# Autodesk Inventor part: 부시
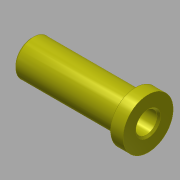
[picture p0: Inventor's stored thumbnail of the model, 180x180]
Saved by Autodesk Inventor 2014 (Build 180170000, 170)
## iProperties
Created: 2016-11
Part Number: 부시
Material: 강철, 연강
Document SubType Name: Modeling
Designer: mduedu
Density: 1 g/cm^3
Appearance: Yellow
Author: mduedu
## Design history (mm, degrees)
sketch "스케치1"
  geometry: L1 (0, 0)-(65, 0); L2 (65, 0)-(65, 14); L3 (65, 14)-(58, 14); L4 (58, 14)-(58, 10); L5 (58, 10)-(0, 10); L6 (0, 10)-(0, 0)
  constraints: 12 end point, 3 parallel, 2 perpendicular, 1 horizontal
  dimensions: "d0" = 65 distance of L1.start L1.end; "d1" = 7 distance of L2.end L3.end; "d2" = 28 diameter of L3 L1; "d3" = 20 diameter of L5 L1
revolve "회전1" sketch "스케치1" stored, may be unused: angle "d4" = 90 deg
hole "구멍1" diameter "d7" = 12; stored, may be unused: countersink angle "d11" = 90 deg, drill point angle "d13" = 118 deg; dims "d5" = 10, "d6" = 10, "d8" = 6, "d9" = 4, "d10" = 2, "d12" = 8
chamfer "모따기1" distance "d14" = 1; stored, may be unused: second distance "d15" = 2, angle "d16" = 45 deg
node "솔리드1"
